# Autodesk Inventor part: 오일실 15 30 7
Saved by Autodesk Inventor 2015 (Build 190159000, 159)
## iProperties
Created: 2025-08
Part Number: 오일실 15 30 7
Material: 일반
Document SubType Name: Modeling
Designer: user
Density: 1 g/cm^3
Appearance: 기본값
Author: jhkim
Description: 오일-실
Creation Date: 2025-08-05
Sending System: Autodesk Inventor 2026
Preprocessor: ST-DEVELOPER v20.1
Author: user
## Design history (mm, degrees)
node "오일실 15 30 71"
body "Solid1"
node "기준1"
